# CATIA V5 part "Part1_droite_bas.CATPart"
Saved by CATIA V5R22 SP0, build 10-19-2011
Part number: Part1
Bounding box of the stored display mesh (mm): x 0 to 89.5, y -87.5 to 89.999, z 0 to 150
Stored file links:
  C:\Users\dussa\Documents\ENIB\S5\inter\Part1_droite_bas.CATPart
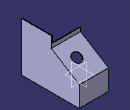
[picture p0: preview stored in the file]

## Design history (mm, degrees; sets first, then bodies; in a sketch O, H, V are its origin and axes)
Body1 (main body)
  Sketch1 on xy-plane, origin (0, 0, 0), H (1, 0, 0), V (0, 1, 0)
    line L1 (-87.5, 87.5) -> (87.5, 87.5)
    line L2 (87.5, 87.5) -> (87.5, -87.5)
    line L3 (87.5, -87.5) -> (-87.5, -87.5)
    line L4 (-87.5, -87.5) -> (-87.5, 87.5)
    distance L1 L3 = 175
    distance L4 L2 = 175
    horizontal: L1 H, L3 H
    vertical: L2 V, L4 V
    symmetry: L3 L1 H, L4 L2 V
  Pad1: profile Sketch1, direction (0, 0, 1), length 2
  Sketch2 on face of Pad1 from Sketch1.L2, origin (87.5, 0, 0), H (0, 1, 0), V (0, 0, 1)
    point P1 (-87.5, 0)
    line L1 (-87.5, 0) -> (87.5, 0)
    line L2 (87.5, 0) -> (87.5, 62.3217)
    line L3 (-87.5, 80) -> (-87.5, 0)
    point P3 (87.5, 62.3217)
    point P4 (-87.5, 80)
    reference projected line E1 (-87.5, 0) -> (-87.5, 2) from edge [face of Pad1 from Sketch1.L2 | face of Pad1 from Sketch1.L3]
    reference projected line E2 (87.5, 0) -> (87.5, 2) from edge [face of Pad1 from Sketch1.L1 | face of Pad1 from Sketch1.L2]
    reference projected line E3 (-87.5, 0) -> (87.5, 0) from edge [start face of Pad1 | face of Pad1 from Sketch1.L2]
    line L4 (-87.5, 300) -> (2.5, 300)
    line L5 (2.5, 300) -> (2.5, 115)
    line L6 (-87.5, 80) -> (-87.5, 300)
    point P8 (-87.5, 80)
    line L7 (2.5, 115) -> (87.5, 62.3217)
    point P9 (87.5, 62.3217)
    distance P4 P1 = 80
    distance L1 L4 = 300
    length L5 = 185
    distance L5 L6 = 90
    length L7 = 100
    horizontal: L1 H, L4 H
    vertical: L2 V, L3 V, L5 V, L6 V
    coincidence: E1 L3, L2 E2, L1 E3, L6 L3, P8 P4, L7 P3, P3 P9
  Pad2: profile Sketch2, direction (1, 0, 0), length 2
  Sketch3 on face of Pad1 from Sketch1.L4, origin (-87.5, 0, 0), H (0, 1, 0), V (0, 0, 1)
    point P1 (-87.5, 0)
    line L1 (-87.5, 0) -> (87.5, 0)
    line L2 (87.5, 0) -> (87.5, 62.3217)
    line L3 (-87.5, 80) -> (-87.5, 0)
    point P3 (87.5, 62.3217)
    point P4 (-87.5, 80)
    reference projected line E1 (-87.5, 0) -> (-87.5, 2) from edge [face of Pad1 from Sketch1.L2 | face of Pad1 from Sketch1.L3]
    reference projected line E2 (87.5, 0) -> (87.5, 2) from edge [face of Pad1 from Sketch1.L1 | face of Pad1 from Sketch1.L2]
    reference projected line E3 (-87.5, 0) -> (87.5, 0) from edge [start face of Pad1 | face of Pad1 from Sketch1.L2]
    line L4 (-87.5, 300) -> (2.5, 300)
    line L5 (2.5, 300) -> (2.5, 115)
    line L6 (-87.5, 80) -> (-87.5, 300)
    point P8 (-87.5, 80)
    line L7 (2.5, 115) -> (87.5, 62.3217)
    point P9 (87.5, 62.3217)
    distance P4 P1 = 80
    distance L1 L4 = 300
    length L5 = 185
    distance L5 L6 = 90
    length L7 = 100
    horizontal: L1 H, L4 H
    vertical: L2 V, L3 V, L5 V, L6 V
    coincidence: E1 L3, L2 E2, L1 E3, L6 L3, P8 P4, L7 P3, P3 P9
  Pad3: profile Sketch3, direction (1, 0, 0), length 2
  Sketch4 on face of Pad3 from Sketch3.L4, origin (0, 0, 300), H (1, 0, 0), V (0, 1, 0)
    line L1 (-87.5, 2.5) -> (89.5, 2.5)
    line L2 (89.5, 2.5) -> (89.5, -87.5)
    line L3 (89.5, -87.5) -> (-87.5, -87.5)
    line L4 (-87.5, -87.5) -> (-87.5, 2.5)
    reference projected line E1 (-87.5, -87.5) -> (87.5, -87.5) from edge [face of Pad3 | end face of Pad1]
    reference projected point E2 (89.5, 2.5) from vertex [face of Pad2 from Sketch2.L5 | face of Pad2 from Sketch2.L4 | end face of Pad2]
    reference projected line E3 (-87.5, 2.5) -> (-87.5, -87.5) from edge [start face of Pad3 | face of Pad3 from Sketch3.L4]
    reference projected line E4 (89.5, 2.5) -> (89.5, -87.5) from edge [face of Pad2 from Sketch2.L4 | end face of Pad2]
    horizontal: L1 H, L3 H
    vertical: L2 V, L4 V
    coincidence: L3 E1, L1 E2, L4 E3, E4 L2
  Pad4: profile Sketch4, direction (0, 0, 1), length 2
  Sketch5 on face of Pad3, origin (0, 87.5, 0), H (-1, 0, 0), V (0, 0, 1)
    line L1 (-89.5, 62.3217) -> (87.5, 62.3217)
    line L2 (87.5, 62.3217) -> (87.5, 0)
    line L3 (87.5, 0) -> (-89.5, 0)
    line L4 (-89.5, 0) -> (-89.5, 62.3217)
    reference projected point E1 (85.5, 62.3217) from vertex [end face of Pad3 | face of Pad3 from Sketch3.L2 | face of Pad3 from Sketch3.L7]
    reference projected line E2 (-87.5, 0) -> (87.5, 0) from edge [face of Pad3 | face of Pad3]
    reference projected line E3 (87.5, 0) -> (87.5, 2) from edge [face of Pad3 | face of Pad3]
    reference projected line E4 (-89.5, 0) -> (-89.5, 62.3217) from edge [face of Pad3 | end face of Pad2]
    horizontal: L1 H, L3 H
    vertical: L2 V, L4 V
    coincidence: E1 L1, E2 L3, L2 E3, E4 L4
  Pad5: profile Sketch5, direction (0, 1, 0), length 2
  Sketch6 on face of Pad2 from Sketch2.L7, origin (0, 52.1868, 84.2069), H (-1, 0, 0), V (0, -0.85, 0.5268)
    line L1 (-89.5, 58.455) -> (87.5, 58.455)
    line L2 (87.5, 58.455) -> (87.5, -43.245)
    line L3 (87.5, -43.245) -> (-89.5, -43.245)
    line L4 (-89.5, -43.245) -> (-89.5, 58.455)
    reference projected line E1 (87.5, -43.245) -> (-89.5, -43.245) from edge [face of Pad5 from Sketch5.L1 | end face of Pad5]
    reference projected line E2 (87.5, -41.545) -> (87.5, 58.455) from edge [face of Pad5 | face of Pad3 from Sketch3.L7]
    reference projected line E3 (87.5, 58.455) -> (85.5, 58.455) from edge [face of Pad3 from Sketch3.L5 | face of Pad3 from Sketch3.L7]
    reference projected line E4 (-89.5, -41.545) -> (-89.5, 58.455) from edge [face of Pad2 from Sketch2.L7 | face of Pad5]
    circle A1 centre (-50, 11.755) radius 14.5
    point P5 (-50, 11.755)
    circle A2 centre (50, 11.755) radius 3.35
    point P6 (50, 11.755)
    radius A1 = 14.5
    radius A2 = 3.35
    distance P5 V = 50
    distance P6 V = 50
    distance P5 L3 = 55
    distance P6 L3 = 55
    horizontal: L1 H, L3 H
    vertical: L2 V, L4 V
    coincidence: L3 E1, L2 E2, E3 L1, L4 E4
  Pad6: profile Sketch6, direction (0, 0.5268, 0.85), length 2
  Sketch7 on face of Pad3 from Sketch3.L5, origin (0, 2.5, 0), H (-1, 0, 0), V (0, 0, 1)
    line L1 (-89.5, 302) -> (87.5, 302)
    line L2 (87.5, 302) -> (87.5, 116.7)
    line L3 (87.5, 116.7) -> (-89.5, 116.7)
    line L4 (-89.5, 116.7) -> (-89.5, 302)
    reference projected line E1 (-89.5, 302) -> (87.5, 302) from edge [face of Pad4 from Sketch4.L1 | end face of Pad4]
    reference projected line E2 (87.5, 116.7) -> (-89.5, 116.7) from edge [face of Pad6 from Sketch6.L1 | end face of Pad6]
    reference projected line E3 (-89.5, 115) -> (-89.5, 300) from edge [face of Pad2 from Sketch2.L5 | face of Pad6]
    reference projected line E4 (87.5, 115) -> (87.5, 300) from edge [face of Pad6 | face of Pad3 from Sketch3.L5]
    line L5 (-86, 298.5) -> (84, 298.5)
    line L6 (84, 298.5) -> (84, 128.5)
    line L7 (84, 128.5) -> (-86, 128.5)
    line L8 (-86, 128.5) -> (-86, 298.5)
    distance L6 L8 = 170
    distance L5 L7 = 170
    distance L5 L1 = 3.5
    distance L8 L4 = 3.5
    horizontal: L1 H, L3 H, L5 H, L7 H
    vertical: L2 V, L4 V, L6 V, L8 V
    coincidence: L1 E1, L3 E2, L4 E3, L2 E4
  Pad7: profile Sketch7, direction (0, 1, 0), length 2
  Split1: SplitPlane yz-plane
  Split2: SplitPlane {plane type Offset, RefPlane xy-plane, Offset 150}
